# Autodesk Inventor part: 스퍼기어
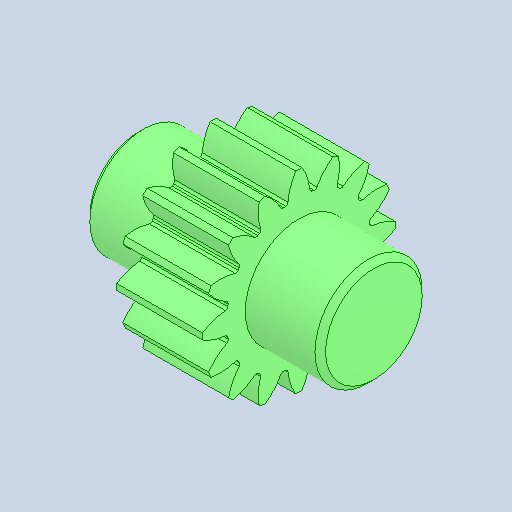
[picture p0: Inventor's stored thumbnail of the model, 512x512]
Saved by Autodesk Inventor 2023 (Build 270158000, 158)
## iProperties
Created: 2025-10
Part Number: 스퍼기어
Material: 강철, 합금
Document SubType Name: Modeling
Designer: home
Density: 7.73 g/cm^3
Appearance: 기본값
Author: jhkim
Sending System: Autodesk Inventor 2026
Preprocessor: ST-DEVELOPER v20.1
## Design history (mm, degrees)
feature "솔리드1"
node "솔리드2"
